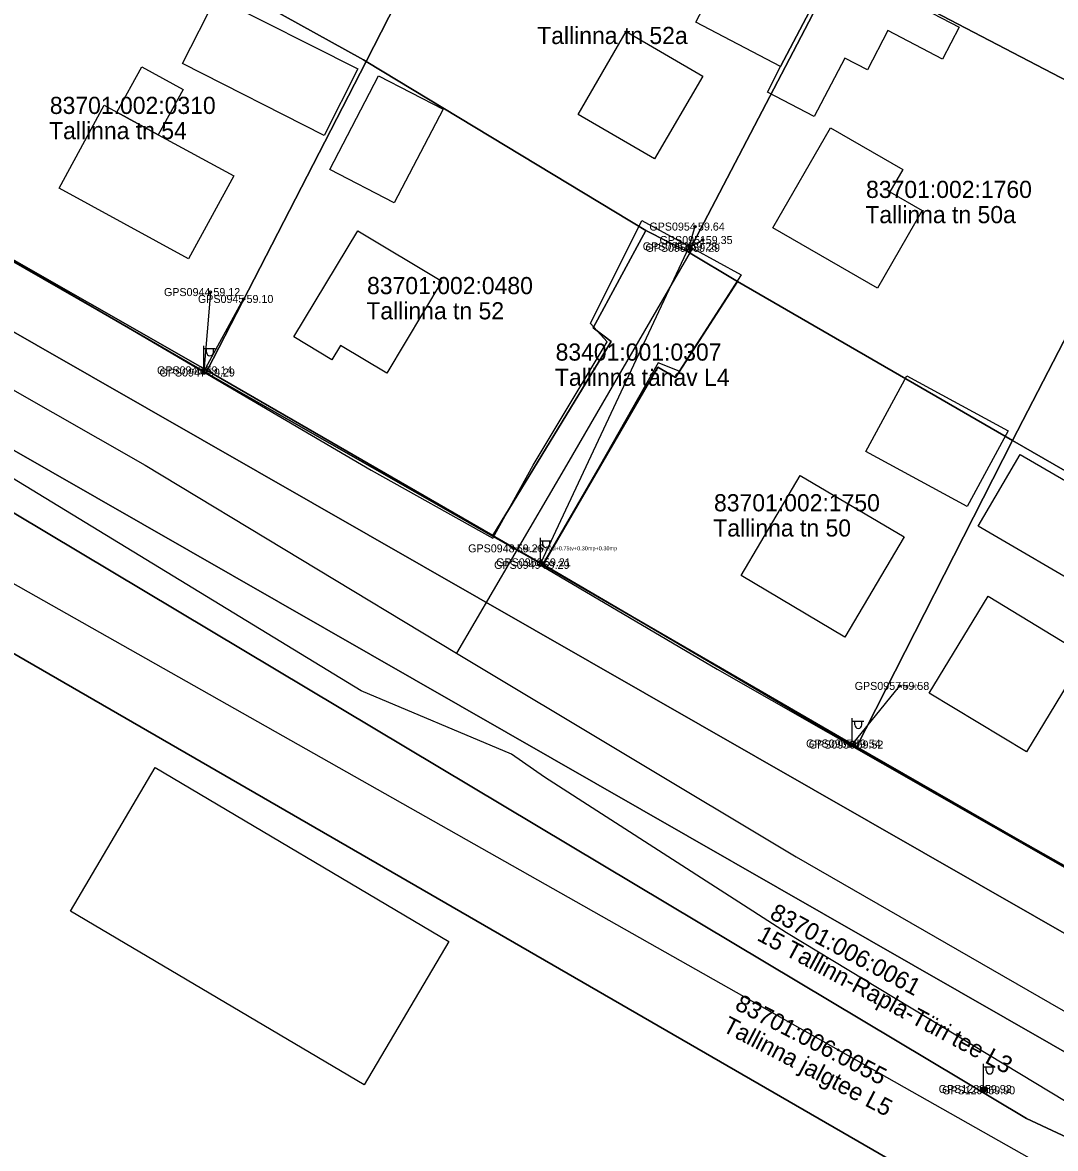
# Model space of a CAD drawing. Extents: x 580119 to 583377, y 6518915 to 6520820.
# Drawn here: x 581401 to 581491.3, y 6519940.2 to 6520038.7 of the extents above; entities that cross this region are included whole.
import ezdxf

# ---------------------------------------------------------------- set-up
doc = ezdxf.new("R2010")
doc.units = 0
for name, color, linetype in [('Hoone Elu- või ühiskondlik hoone', 7, 'Continuous'), ('Hoone Kõrval- või tootmishoone', 7, 'Continuous'), ('L_AADRESS', 7, 'Continuous'), ('MAAMUDEL', 7, 'Continuous'), ('MOOTKORG-EH2000', 7, 'Continuous'), ('MOOTMPUNKT', 7, 'Continuous'), ('MOOTNR', 7, 'Continuous'), ('MPOHULIIN', 7, 'Continuous'), ('PIIR', 7, 'Continuous'), ('POST', 7, 'Continuous'), ('Rippe kõrgus', 7, 'Continuous'), ('SIOHULIIN', 7, 'Continuous'), ('Tee Kergliiklustee Püsikate', 7, 'Continuous'), ('Tee Liiklusala', 7, 'Continuous'), ('Tee Tugimaantee Püsikate', 7, 'Continuous'), ('Tee Tänav Püsikate', 7, 'Continuous'), ('TUNNUS', 7, 'Continuous')]:
    doc.layers.add(name, color=color, linetype=linetype)

msp = doc.modelspace()

# ---------------------------------------------------------------- linework, layer by layer
at = {"layer": 'Hoone Elu- või ühiskondlik hoone'}
for points in [[(581460.489, 6520034.027), (581456.279, 6520026.791), (581449.596, 6520030.678), (581453.796, 6520037.919)], [(581409.277, 6520030.871), (581412.893, 6520028.897), (581419.496, 6520025.288), (581415.547, 6520018.052), (581404.225, 6520024.235), (581408.166, 6520031.478)], [(581479.684, 6520022.263), (581475.768, 6520015.468), (581466.629, 6520020.743), (581471.678, 6520029.494), (581477.979, 6520025.868), (581476.844, 6520023.898)], [(581437.697, 6520016.081), (581432.86, 6520008.03), (581428.821, 6520010.46), (581428.073, 6520009.216), (581424.747, 6520011.218), (581430.327, 6520020.502)], [(581478.106, 6519993.726), (581472.926, 6519984.968), (581463.841, 6519990.342), (581469.021, 6519999.1)], [(581493.936, 6519983.379), (581488.803, 6519974.917), (581480.304, 6519980.068), (581485.451, 6519988.53)]]:
    msp.add_lwpolyline(points, close=True, dxfattribs=at)
at = {"layer": 'Hoone Kõrval- või tootmishoone'}
for points in [[(581472.071, 6520043.963), (581467.306, 6520034.853), (581459.877, 6520038.738), (581464.645, 6520047.847)], [(581482.908, 6520038.295), (581481.447, 6520035.51), (581476.692, 6520038), (581474.892, 6520034.575), (581472.924, 6520035.599), (581470.241, 6520030.483), (581466.144, 6520032.624), (581467.306, 6520034.853), (581472.071, 6520043.963)], [(581430.346, 6520034.658), (581427.391, 6520028.839), (581415.005, 6520035.133), (581417.964, 6520040.937)], [(581415.058, 6520032.866), (581412.893, 6520028.897), (581409.277, 6520030.871), (581411.446, 6520034.833)], [(581437.788, 6520031.126), (581433.525, 6520022.934), (581427.889, 6520025.864), (581432.145, 6520034.048)], [(581487.208, 6520002.993), (581483.624, 6519996.393), (581474.757, 6520001.207), (581478.345, 6520007.801)], [(581498.543, 6519994.955), (581494.873, 6519988.662), (581484.582, 6519994.667), (581488.252, 6520000.945)], [(581438.307, 6519958.342), (581430.881, 6519945.799), (581405.203, 6519961.006), (581412.63, 6519973.554)]]:
    msp.add_lwpolyline(points, close=True, dxfattribs=at)
at = {"layer": 'MOOTMPUNKT'}
for centre in [(581459.816, 6520020.865), (581460.499, 6520019.688), (581459.169, 6520019.136), (581459.402, 6520019.007), (581417.449, 6520015.135), (581420.35, 6520014.535), (581416.771, 6520008.295), (581416.983, 6520008.102), (581443.975, 6519992.723), (581446.245, 6519991.28), (581446.35, 6519991.502), (581477.698, 6519980.693), (581473.45, 6519975.657), (581473.685, 6519975.563), (581484.904, 6519945.441), (581485.204, 6519945.329)]:
    msp.add_circle(centre, 0.1, dxfattribs=at)
at = {"layer": 'MPOHULIIN'}
for p, q in [((581459.816, 6520020.865), (581459.285, 6520019.071)), ((581460.499, 6520019.688), (581459.285, 6520019.071)), ((581459.285, 6520019.071), (581446.297, 6519991.391)), ((581477.698, 6519980.693), (581473.567, 6519975.61))]:
    msp.add_line(p, q, dxfattribs=at)
for points in [[(581386.073, 6520026.019), (581416.877, 6520008.198), (581446.297, 6519991.391), (581473.567, 6519975.61), (581504.784, 6519957.665), (581539.717, 6519936.988), (581580.339, 6519912.712), (581617.797, 6519889.378), (581651.138, 6519869.543), (581688.963, 6519846.821), (581727.775, 6519823.511), (581768.986, 6519798.831), (581799.645, 6519779.996), (581800.763, 6519769.028)], [(581417.449, 6520015.135), (581416.877, 6520008.198), (581420.35, 6520014.535)]]:
    msp.add_lwpolyline(points, dxfattribs=at)
at = {"layer": 'PIIR'}
for points in [[(581488.22, 6520074.9), (581517.28, 6520059.91), (581514.94, 6520055.34), (581501.39, 6520028.88), (581472.48, 6520044)], [(581399.85, 6520052.55), (581408.78, 6520069.58), (581439.6, 6520052.04), (581431.08, 6520035.3), (581430.82, 6520035.45), (581400.17, 6520052.43)], [(581439.6, 6520052.04), (581443.23, 6520058.84), (581472.48, 6520044), (581459.24, 6520018.64), (581455.53, 6520020.52), (581431.08, 6520035.3)], [(581399.85, 6520052.55), (581400.17, 6520052.43), (581430.82, 6520035.45), (581431.08, 6520035.3), (581417.16, 6520008.29), (581386.35, 6520025.87)], [(581314, 6520033.36), (581483.99, 6519935.14), (581474.08, 6519918.16), (581469.95, 6519920.52), (581465.84, 6519913.25), (581469.89, 6519910.94), (581441.15, 6519861.53), (581432.72, 6519846.75), (581335.95, 6519901.99), (581308.73, 6519916.22), (581310.08, 6519918.55), (581213.15, 6519973.93), (581214.93, 6519985.52), (581215, 6519986.31), (581250.08, 6520048.4), (581263.65, 6520040.92), (581266.61, 6520041.64), (581256.22, 6520026.21), (581295.9, 6520003.32)], [(581459.24, 6520018.64), (581472.48, 6520044), (581501.39, 6520028.88), (581487.59, 6520002.15), (581463.52, 6520016.06)], [(581431.08, 6520035.3), (581455.53, 6520020.52), (581450.91, 6520012), (581452.5, 6520010.82), (581442.14, 6519993.86), (581417.16, 6520008.29)], [(581501.39, 6520028.88), (581533.69, 6520012.27), (581519.2, 6519983.94), (581487.59, 6520002.15)], [(581363.85, 6520022.11), (581562.34, 6519908.5), (581488.8, 6519942.86), (581385.98, 6520004.33)], [(581446.53, 6519991.3), (581442.14, 6519993.86), (581452.5, 6520010.82), (581450.91, 6520012), (581455.53, 6520020.52), (581459.24, 6520018.64), (581463.52, 6520016.06), (581458.12, 6520007.67), (581456.56, 6520008.58)], [(581456.56, 6520008.58), (581458.12, 6520007.67), (581463.52, 6520016.06), (581487.59, 6520002.15), (581473.92, 6519975.28), (581446.53, 6519991.3)], [(581487.59, 6520002.15), (581519.2, 6519983.94), (581505.33, 6519957.51), (581473.92, 6519975.28)]]:
    msp.add_lwpolyline(points, close=True, dxfattribs=at)
for points in [[(581689.84, 6519815.63), (581631.91, 6519849.33), (581575.03, 6519882.38), (581543.14, 6519900.86), (581505.13, 6519922.94), (581483.99, 6519935.14), (581314, 6520033.36)], [(581761.13, 6519789.94), (581562.34, 6519908.5), (581363.85, 6520022.11), (581368.33, 6520029.92), (581566.91, 6519916.24), (581765.76, 6519797.71)], [(581765.76, 6519797.71), (581566.91, 6519916.24), (581368.33, 6520029.92)], [(581386.35, 6520025.87), (581417.16, 6520008.29), (581442.14, 6519993.86), (581446.53, 6519991.3), (581473.92, 6519975.28), (581505.33, 6519957.51), (581518.19, 6519949.74), (581546.98, 6519932.72), (581562.55, 6519923.42), (581578.78, 6519913.69), (581589.04, 6519907.54), (581618.38, 6519889.95), (581645.47, 6519873.21), (581677.12, 6519854.1), (581713.07, 6519832.45), (581720.83, 6519828.38), (581751.53, 6519809.56)], [(581385.98, 6520004.33), (581488.8, 6519942.86), (581562.34, 6519908.5), (581761.13, 6519789.94)]]:
    msp.add_lwpolyline(points, dxfattribs=at)
at = {"layer": 'POST'}
for p, q in [((581416.877, 6520008.448), (581416.877, 6520010.448)), ((581416.877, 6520010.198), (581417.877, 6520010.198)), ((581417.104, 6520009.878), (581417.104, 6520010.198)), ((581417.717, 6520009.878), (581417.717, 6520010.198)), ((581416.877, 6520008.198), (581416.877, 6520008.198)), ((581446.297, 6519991.641), (581446.297, 6519993.641)), ((581446.297, 6519993.391), (581447.297, 6519993.391)), ((581446.524, 6519993.07), (581446.524, 6519993.391)), ((581447.137, 6519993.07), (581447.137, 6519993.391)), ((581446.297, 6519991.391), (581446.297, 6519991.391)), ((581473.567, 6519975.86), (581473.567, 6519977.86)), ((581473.567, 6519977.61), (581474.567, 6519977.61)), ((581473.794, 6519977.289), (581473.794, 6519977.61)), ((581474.407, 6519977.289), (581474.407, 6519977.61)), ((581473.567, 6519975.61), (581473.567, 6519975.61)), ((581485.054, 6519945.635), (581485.054, 6519947.635)), ((581485.054, 6519947.385), (581486.054, 6519947.385)), ((581485.281, 6519947.064), (581485.281, 6519947.385)), ((581485.894, 6519947.064), (581485.894, 6519947.385)), ((581485.054, 6519945.385), (581485.054, 6519945.385))]:
    msp.add_line(p, q, dxfattribs=at)
for centre, radius in [((581459.285, 6520019.071), 0.25), ((581416.877, 6520008.198), 0.25), ((581446.297, 6519991.391), 0.25), ((581473.567, 6519975.61), 0.25), ((581485.054, 6519945.385), 0.25), ((581485.054, 6519945.385), 0.225), ((581485.054, 6519945.385), 0.2), ((581485.054, 6519945.385), 0.175), ((581485.054, 6519945.385), 0.15), ((581485.054, 6519945.385), 0.125), ((581485.054, 6519945.385), 0.1), ((581485.054, 6519945.385), 0.075), ((581485.054, 6519945.385), 0.05), ((581485.054, 6519945.385), 0.025)]:
    msp.add_circle(centre, radius, dxfattribs=at)
for centre in [(581417.41, 6520009.878), (581446.83, 6519993.07), (581474.1, 6519977.289), (581485.587, 6519947.064)]:
    msp.add_arc(centre, 0.306, 180, 0, dxfattribs=at)
at = {"layer": 'SIOHULIIN'}
msp.add_lwpolyline([(581504.784, 6519957.665), (581473.567, 6519975.61), (581446.297, 6519991.391), (581416.877, 6520008.198), (581386.073, 6520026.019)], dxfattribs=at)
at = {"layer": 'Tee Kergliiklustee Püsikate'}
msp.add_lwpolyline([(581270.06, 6520065.002), (581303.35, 6520046.088), (581363.49, 6520010.551), (581381.906, 6520000), (581491.25, 6519938.16)], dxfattribs=at)
at = {"layer": 'Tee Liiklusala'}
for points in [[(581388.572, 6520024.456), (581410.638, 6520011.791), (581431.495, 6519999.57), (581442.131, 6519993.617), (581445.675, 6520000), (581452.148, 6520010.795), (581450.685, 6520012.385), (581455.17, 6520021.41), (581459.59, 6520018.982), (581463.84, 6520016.64), (581458.447, 6520008.22), (581456.586, 6520008.935), (581451.427, 6519999.856), (581446.426, 6519991.185), (581461.743, 6519982.17), (581505.117, 6519957.414), (581508.839, 6519955.411), (581509.984, 6519955.983), (581526.726, 6519988.621), (581532.685, 6520000.001), (581553.146, 6520039.174)], [(581495.594, 6519939.129), (581492.272, 6519944.314), (581467.804, 6519959.088), (581446.667, 6519972.717), (581443.772, 6519974.73), (581430.641, 6519980.267), (581387.111, 6520006.796)]]:
    msp.add_lwpolyline(points, dxfattribs=at)
at = {"layer": 'Tee Tugimaantee Püsikate'}
for points in [[(581375.286, 6520020.77), (581411.735, 6520000), (581438.978, 6519983.551)], [(581438.978, 6519983.551), (581468.666, 6519965.739), (581506.086, 6519944.195)]]:
    msp.add_lwpolyline(points, dxfattribs=at)
at = {"layer": 'Tee Tänav Püsikate'}
msp.add_lwpolyline([(581459.59, 6520018.982), (581448.571, 6520000), (581438.978, 6519983.551)], dxfattribs=at)

# ---------------------------------------------------------------- texts
at = {"layer": 'L_AADRESS'}
for s, p in [('Tallinna tn 52a', (581446.019, 6520036.827)), ('Tallinna tn 54', (581403.345, 6520028.507)), ('Tallinna tn 50a', (581474.711, 6520021.162)), ('Tallinna tn 52', (581431.082, 6520012.75)), ('Tallinna tänav L4', (581447.567, 6520006.935)), ('Tallinna tn 50', (581461.416, 6519993.757))]:
    msp.add_text(s, height=1.5, dxfattribs=at).set_placement(p)
for s, rotation, p in [('15 Tallinn-Rapla-Türi tee L3', 331.71626, (581465.15, 6519958.503)), ('Tallinna jalgtee L5', 332.41936, (581462.129, 6519950.536))]:
    msp.add_text(s, height=1.5, rotation=rotation, dxfattribs=at).set_placement(p)
at = {"layer": 'MAAMUDEL'}
for s, p in [(' si', (581416.771, 6520008.12)), (' si', (581416.983, 6520007.927)), (' si', (581446.245, 6519991.105)), (' si', (581446.35, 6519991.327)), (' mp_ohl', (581477.698, 6519980.518)), (' si', (581473.45, 6519975.482)), (' si', (581473.685, 6519975.388))]:
    msp.add_text(s, height=0.35, dxfattribs=at).set_placement(p)
at = {"layer": 'MOOTKORG-EH2000'}
for s, p in [(' 59.64', (581459.816, 6520020.515)), (' 59.28', (581459.169, 6520018.786)), (' 59.35', (581460.499, 6520019.338)), (' 59.29', (581459.402, 6520018.657)), (' 59.12', (581417.449, 6520014.785)), (' 59.10', (581420.35, 6520014.185)), (' 59.14', (581416.771, 6520007.945)), (' 59.29', (581416.983, 6520007.752)), (' 59.26', (581443.975, 6519992.373)), (' 59.21', (581446.35, 6519991.152)), (' 59.29', (581446.245, 6519990.93)), (' 59.58', (581477.698, 6519980.343)), (' 59.54', (581473.45, 6519975.307)), (' 59.52', (581473.685, 6519975.213)), (' 59.92', (581484.904, 6519945.091)), (' 59.90', (581485.204, 6519944.979))]:
    msp.add_text(s, height=0.7, dxfattribs=at).set_placement(p)
at = {"layer": 'MOOTNR'}
for s, p in [('GPS0954 ', (581455.827, 6520020.515)), ('GPS0952 ', (581455.249, 6520018.786)), ('GPS0951 ', (581456.719, 6520019.338)), ('GPS0953 ', (581455.482, 6520018.657)), ('GPS0944 ', (581413.389, 6520014.785)), ('GPS0945 ', (581416.36, 6520014.185)), ('GPS0946 ', (581412.781, 6520007.945)), ('GPS0947 ', (581412.994, 6520007.752)), ('GPS0948 ', (581439.985, 6519992.373)), ('GPS0950 ', (581442.43, 6519991.152)), ('GPS0949 ', (581442.256, 6519990.93)), ('GPS0957 ', (581473.778, 6519980.343)), ('GPS0955 ', (581469.53, 6519975.307)), ('GPS0956 ', (581469.765, 6519975.213)), ('GPS1289 ', (581481.124, 6519945.091)), ('GPS1290 ', (581481.424, 6519944.979))]:
    msp.add_text(s, height=0.7, dxfattribs=at).set_placement(p)
at = {"layer": 'Rippe kõrgus'}
msp.add_text(' el_mp_ohl6.20si+0.75tv+0.30mp+0.30mp', height=0.35, dxfattribs=at).set_placement((581443.975, 6519992.548))
at = {"layer": 'TUNNUS'}
for s, p in [('83701:002:0310', (581403.409, 6520030.712)), ('83701:002:1760', (581474.774, 6520023.367)), ('83701:002:0480', (581431.145, 6520014.955)), ('83401:001:0307', (581447.63, 6520009.14)), ('83701:002:1750', (581461.48, 6519995.962))]:
    msp.add_text(s, height=1.5, dxfattribs=at).set_placement(p)
for s, rotation, p in [('83701:006:0061', 331.71626, (581466.251, 6519960.414)), ('83701:006:0055', 332.41936, (581463.207, 6519952.461))]:
    msp.add_text(s, height=1.5, rotation=rotation, dxfattribs=at).set_placement(p)

doc.saveas('drawing.dxf')
